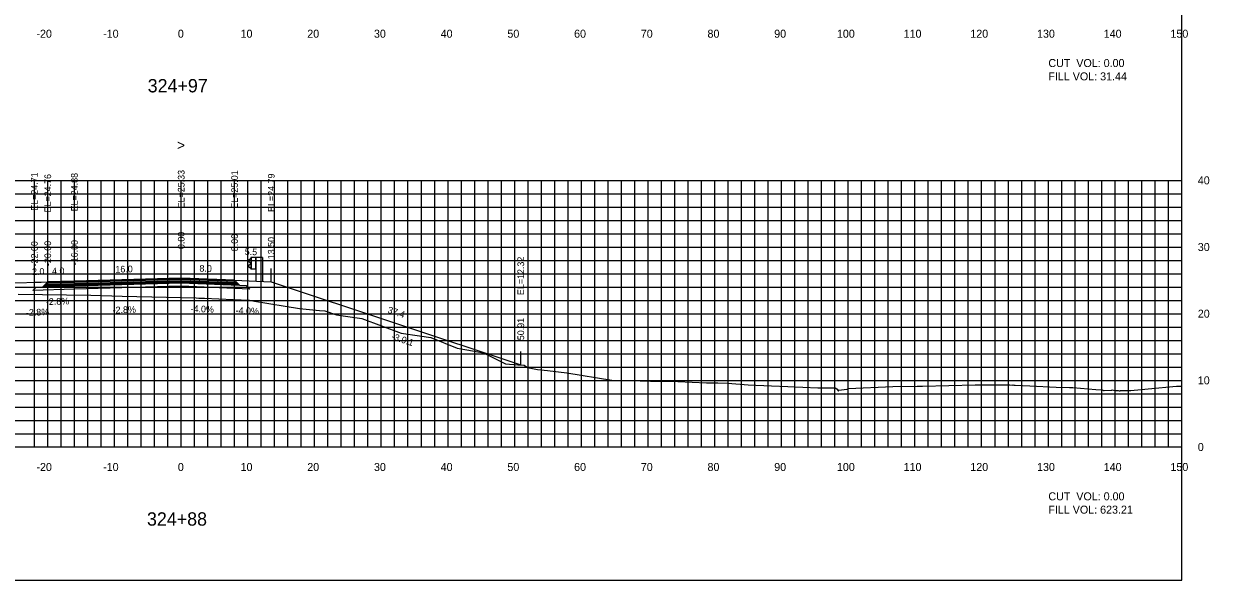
# Model space of a CAD drawing. Extents: x 1797652 to 1804145, y 245981 to 250269.
# Drawn here: x 1803967.4 to 1804145.1, y 250079.4 to 250162.9 of the extents above; entities that cross this region are included whole.
import ezdxf

# ---------------------------------------------------------------- set-up
doc = ezdxf.new("R2010")
doc.units = 0
for name, color, linetype in [('1', 7, 'Continuous'), ('10', 7, 'Continuous'), ('3', 7, 'Continuous'), ('31', 7, 'Continuous'), ('4', 7, 'Continuous'), ('60', 7, 'Continuous'), ('ANNO-TXT', 7, 'Continuous'), ('BASE', 7, 'Continuous'), ('CL-CNST', 7, 'Continuous'), ('Level 1', 7, 'Continuous'), ('Level 62', 7, 'Continuous'), ('LOWER BINDER', 7, 'Continuous'), ('M-ROADS', 7, 'Continuous'), ('UPPER BINDER', 7, 'Continuous'), ('WEARING', 7, 'Continuous')]:
    doc.layers.add(name, color=color, linetype=linetype)

msp = doc.modelspace()

# ---------------------------------------------------------------- linework, layer by layer
for p, q in [((1803971, 250124.19), (1803971, 250126.19)), ((1803975, 250124.31), (1803975, 250126.31)), ((1803991, 250124.76), (1803991, 250126.76)), ((1803999, 250124.44), (1803999, 250126.44)), ((1804004.5, 250124.22), (1804004.5, 250126.22)), ((1803969, 250124.14), (1803969, 250126.14)), ((1804041.91, 250111.75), (1804041.91, 250113.75))]:
    msp.add_line(p, q)
msp.add_lwpolyline([(1803841, 250079.43), (1804141, 250079.43), (1804141, 250269.43), (1803841, 250269.43)], close=True)
at = {"layer": '60'}
for p, q in [((1804141, 250099.43), (1804141, 250139.43)), ((1804141.06, 250139.43), (1804141, 250139.43)), ((1804141.06, 250129.43), (1804141, 250129.43)), ((1804141.06, 250119.43), (1804141, 250119.43)), ((1804141.06, 250109.43), (1804141, 250109.43)), ((1803841, 250099.43), (1804141, 250099.43)), ((1803971, 250099.37), (1803971, 250099.43)), ((1803981, 250099.37), (1803981, 250099.43)), ((1803991, 250099.37), (1803991, 250099.43)), ((1804001, 250099.37), (1804001, 250099.43)), ((1804011, 250099.37), (1804011, 250099.43)), ((1804021, 250099.37), (1804021, 250099.43)), ((1804031, 250099.37), (1804031, 250099.43)), ((1804041, 250099.37), (1804041, 250099.43)), ((1804051, 250099.37), (1804051, 250099.43)), ((1804061, 250099.37), (1804061, 250099.43)), ((1804071, 250099.37), (1804071, 250099.43)), ((1804081, 250099.37), (1804081, 250099.43)), ((1804091, 250099.37), (1804091, 250099.43)), ((1804101, 250099.37), (1804101, 250099.43)), ((1804111, 250099.37), (1804111, 250099.43)), ((1804121, 250099.37), (1804121, 250099.43)), ((1804131, 250099.37), (1804131, 250099.43)), ((1804141, 250099.37), (1804141, 250099.43)), ((1804141.06, 250099.43), (1804141, 250099.43))]:
    msp.add_line(p, q, dxfattribs=at)
at = {"layer": 'BASE'}
msp.add_lwpolyline([(1803969.26, 250123.43), (1803970.26, 250123.45), (1803975, 250123.59), (1803991, 250124.04), (1803999.75, 250123.69), (1804000.75, 250123.65), (1804001.27, 250123.13), (1803991, 250123.54), (1803975, 250123.09), (1803968.75, 250122.91)], close=True, dxfattribs=at)
at = {"layer": 'CL-CNST'}
for points in [[(1803969, 250124.14), (1803971, 250124.19), (1803975, 250124.31), (1803991, 250124.76), (1803999, 250124.44), (1804004.5, 250124.22), (1804041.91, 250111.75)], [(1803965.67, 250124.04), (1803974.37, 250124.28)]]:
    msp.add_lwpolyline(points, dxfattribs=at)
at = {"layer": 'Level 1'}
for p, q in [((1804001.46, 250127.69), (1804001.1, 250127.39)), ((1804001.1, 250127.32), (1804001.46, 250127.03)), ((1804001.46, 250126.89), (1804001.1, 250126.59)), ((1804001.1, 250126.52), (1804001.46, 250126.24)), ((1804001.46, 250127.84), (1804001.46, 250126.09)), ((1804003.21, 250127.84), (1804001.46, 250127.84)), ((1804001.51, 250127.84), (1804001.51, 250126.09)), ((1804002.16, 250127.84), (1804002.16, 250126.09)), ((1804002.21, 250127.84), (1804002.21, 250124.31)), ((1804003.21, 250127.84), (1804003.21, 250124.27)), ((1804002.21, 250126.09), (1804001.46, 250126.09))]:
    msp.add_line(p, q, dxfattribs=at)
for centre in [(1804001.13, 250127.35), (1804001.13, 250126.56)]:
    msp.add_arc(centre, 0.05, 135, 226.6208, dxfattribs=at)
at = {"layer": 'Level 62'}
for p, q in [((1803841, 250139.43), (1804141, 250139.43)), ((1803969, 250099.43), (1803969, 250139.43)), ((1803971, 250099.43), (1803971, 250139.43)), ((1803973, 250099.43), (1803973, 250139.43)), ((1803975, 250099.43), (1803975, 250139.43)), ((1803977, 250099.43), (1803977, 250139.43)), ((1803979, 250099.43), (1803979, 250139.43)), ((1803981, 250099.43), (1803981, 250139.43)), ((1803983, 250099.43), (1803983, 250139.43)), ((1803985, 250099.43), (1803985, 250139.43)), ((1803987, 250099.43), (1803987, 250139.43)), ((1803989, 250099.43), (1803989, 250139.43)), ((1803991, 250099.43), (1803991, 250139.43)), ((1803993, 250099.43), (1803993, 250139.43)), ((1803995, 250099.43), (1803995, 250139.43)), ((1803997, 250099.43), (1803997, 250139.43)), ((1803999, 250099.43), (1803999, 250139.43)), ((1804001, 250099.43), (1804001, 250139.43)), ((1804003, 250099.43), (1804003, 250139.43)), ((1804005, 250099.43), (1804005, 250139.43)), ((1804007, 250099.43), (1804007, 250139.43)), ((1804009, 250099.43), (1804009, 250139.43)), ((1804011, 250099.43), (1804011, 250139.43)), ((1804013, 250099.43), (1804013, 250139.43)), ((1804015, 250099.43), (1804015, 250139.43)), ((1804017, 250099.43), (1804017, 250139.43)), ((1804019, 250099.43), (1804019, 250139.43)), ((1804021, 250099.43), (1804021, 250139.43)), ((1804023, 250099.43), (1804023, 250139.43)), ((1804025, 250099.43), (1804025, 250139.43)), ((1804027, 250099.43), (1804027, 250139.43)), ((1804029, 250099.43), (1804029, 250139.43)), ((1804031, 250099.43), (1804031, 250139.43)), ((1804033, 250099.43), (1804033, 250139.43)), ((1804035, 250099.43), (1804035, 250139.43)), ((1804037, 250099.43), (1804037, 250139.43)), ((1804039, 250099.43), (1804039, 250139.43)), ((1804041, 250099.43), (1804041, 250139.43)), ((1804043, 250099.43), (1804043, 250139.43)), ((1804045, 250099.43), (1804045, 250139.43)), ((1804047, 250099.43), (1804047, 250139.43)), ((1804049, 250099.43), (1804049, 250139.43)), ((1804051, 250099.43), (1804051, 250139.43)), ((1804053, 250099.43), (1804053, 250139.43)), ((1804055, 250099.43), (1804055, 250139.43)), ((1804057, 250099.43), (1804057, 250139.43)), ((1804059, 250099.43), (1804059, 250139.43)), ((1804061, 250099.43), (1804061, 250139.43)), ((1804063, 250099.43), (1804063, 250139.43)), ((1804065, 250099.43), (1804065, 250139.43)), ((1804067, 250099.43), (1804067, 250139.43)), ((1804069, 250099.43), (1804069, 250139.43)), ((1804071, 250099.43), (1804071, 250139.43)), ((1804073, 250099.43), (1804073, 250139.43)), ((1804075, 250099.43), (1804075, 250139.43)), ((1804077, 250099.43), (1804077, 250139.43)), ((1804079, 250099.43), (1804079, 250139.43)), ((1804081, 250099.43), (1804081, 250139.43)), ((1804083, 250099.43), (1804083, 250139.43)), ((1804085, 250099.43), (1804085, 250139.43)), ((1804087, 250099.43), (1804087, 250139.43)), ((1804089, 250099.43), (1804089, 250139.43)), ((1804091, 250099.43), (1804091, 250139.43)), ((1804093, 250099.43), (1804093, 250139.43)), ((1804095, 250099.43), (1804095, 250139.43)), ((1804097, 250099.43), (1804097, 250139.43)), ((1804099, 250099.43), (1804099, 250139.43)), ((1804101, 250099.43), (1804101, 250139.43)), ((1804103, 250099.43), (1804103, 250139.43)), ((1804105, 250099.43), (1804105, 250139.43)), ((1804107, 250099.43), (1804107, 250139.43)), ((1804109, 250099.43), (1804109, 250139.43)), ((1804111, 250099.43), (1804111, 250139.43)), ((1804113, 250099.43), (1804113, 250139.43)), ((1804115, 250099.43), (1804115, 250139.43)), ((1804117, 250099.43), (1804117, 250139.43)), ((1804119, 250099.43), (1804119, 250139.43)), ((1804121, 250099.43), (1804121, 250139.43)), ((1804123, 250099.43), (1804123, 250139.43)), ((1804125, 250099.43), (1804125, 250139.43)), ((1804127, 250099.43), (1804127, 250139.43)), ((1804129, 250099.43), (1804129, 250139.43)), ((1804131, 250099.43), (1804131, 250139.43)), ((1804133, 250099.43), (1804133, 250139.43)), ((1804135, 250099.43), (1804135, 250139.43)), ((1804137, 250099.43), (1804137, 250139.43)), ((1804139, 250099.43), (1804139, 250139.43)), ((1804141, 250099.43), (1804141, 250139.43)), ((1803841, 250137.43), (1804141, 250137.43)), ((1803841, 250135.43), (1804141, 250135.43)), ((1803841, 250133.43), (1804141, 250133.43)), ((1803841, 250131.43), (1804141, 250131.43)), ((1803841, 250129.43), (1804141, 250129.43)), ((1803841, 250127.43), (1804141, 250127.43)), ((1803841, 250125.43), (1804141, 250125.43)), ((1803841, 250123.43), (1804141, 250123.43)), ((1803841, 250121.43), (1804141, 250121.43)), ((1803841, 250119.43), (1804141, 250119.43)), ((1803841, 250117.43), (1804141, 250117.43)), ((1803841, 250115.43), (1804141, 250115.43)), ((1803841, 250113.43), (1804141, 250113.43)), ((1803841, 250111.43), (1804141, 250111.43)), ((1803841, 250109.43), (1804141, 250109.43)), ((1803841, 250107.43), (1804141, 250107.43)), ((1803841, 250105.43), (1804141, 250105.43)), ((1803841, 250103.43), (1804141, 250103.43)), ((1803841, 250101.43), (1804141, 250101.43)), ((1803841, 250099.43), (1804141, 250099.43))]:
    msp.add_line(p, q, dxfattribs=at)
at = {"layer": 'LOWER BINDER'}
for points in [[(1803975, 250123.97), (1803991, 250124.42), (1803999.36, 250124.09), (1803999.55, 250123.89), (1803991, 250124.23), (1803975, 250123.78), (1803970.46, 250123.65), (1803970.65, 250123.85)], [(1803975, 250123.78), (1803991, 250124.23), (1803999.55, 250123.89), (1803999.75, 250123.69), (1803991, 250124.04), (1803975, 250123.59), (1803970.26, 250123.45), (1803970.46, 250123.65)]]:
    msp.add_lwpolyline(points, close=True, dxfattribs=at)
at = {"layer": 'M-ROADS'}
msp.add_lwpolyline([(1803966.58, 250122.36), (1803977.43, 250122.19), (1803982.14, 250122.07), (1803993.22, 250121.8), (1803993.64, 250121.78), (1803994.47, 250121.76), (1803998.79, 250121.57), (1804001.26, 250121.45), (1804001.97, 250121.32), (1804008.74, 250120.22), (1804011.71, 250119.93), (1804012.51, 250119.85), (1804014.26, 250119.24), (1804015.29, 250119.1), (1804018.07, 250118.73), (1804024, 250116.52), (1804026.71, 250116.1), (1804028.43, 250115.84), (1804032.36, 250114.25), (1804033.84, 250113.99), (1804036.32, 250113.55), (1804039.61, 250111.9), (1804041.49, 250111.78), (1804042.41, 250111.72), (1804042.9, 250111.37), (1804044.43, 250111.07), (1804045.92, 250110.9), (1804048.82, 250110.56), (1804055.54, 250109.47), (1804058.94, 250109.4), (1804059.8, 250109.38), (1804061.37, 250109.32), (1804062.18, 250109.31), (1804065.44, 250109.27), (1804069.74, 250109.07), (1804071.45, 250109.04), (1804072.94, 250109.02), (1804075.99, 250108.78), (1804079.49, 250108.59), (1804081.95, 250108.5), (1804086.42, 250108.3), (1804088.06, 250108.32), (1804088.84, 250108.32), (1804088.87, 250108.26), (1804088.97, 250108.34), (1804089.35, 250108.1), (1804089.5, 250107.88), (1804089.51, 250107.84), (1804089.53, 250107.88), (1804089.57, 250107.94), (1804090.77, 250108.13), (1804090.94, 250108.04), (1804091.02, 250108.19), (1804097.68, 250108.5), (1804101.31, 250108.54), (1804102.15, 250108.55), (1804110.03, 250108.75), (1804110.55, 250108.75), (1804112.65, 250108.75), (1804114.9, 250108.75), (1804115.04, 250108.75), (1804115.19, 250108.75), (1804115.2, 250108.75), (1804115.63, 250108.71), (1804115.69, 250108.75), (1804115.84, 250108.73), (1804116.04, 250108.69), (1804118.23, 250108.63), (1804122.19, 250108.39), (1804124.16, 250108.37), (1804124.68, 250108.37), (1804128.13, 250108.04), (1804129.08, 250108), (1804129.28, 250107.93), (1804129.35, 250107.93), (1804130.51, 250107.97), (1804130.57, 250108.01), (1804130.95, 250107.92), (1804131.32, 250107.91), (1804131.46, 250107.91), (1804131.6, 250107.88), (1804131.78, 250107.85), (1804131.8, 250107.93), (1804131.81, 250107.93), (1804131.95, 250107.93), (1804133.38, 250107.93), (1804135.94, 250108.17), (1804140.2, 250108.56), (1804140.92, 250108.56), (1804141, 250108.59)], dxfattribs=at)
at = {"layer": 'UPPER BINDER'}
msp.add_lwpolyline([(1803999.36, 250124.09), (1803999.16, 250124.29), (1803991, 250124.61), (1803975, 250124.16), (1803970.85, 250124.04), (1803970.65, 250123.85), (1803975, 250123.97), (1803991, 250124.42)], close=True, dxfattribs=at)
at = {"layer": 'WEARING'}
msp.add_lwpolyline([(1803999.16, 250124.29), (1803999, 250124.44), (1803991, 250124.76), (1803975, 250124.31), (1803971, 250124.19), (1803970.85, 250124.04), (1803975, 250124.16), (1803991, 250124.61)], close=True, dxfattribs=at)

# ---------------------------------------------------------------- texts
msp.add_text('-3.0:1', height=1, rotation=341.5652).set_placement((1804022.41, 250115.62))
at = {"layer": '1'}
for s, p in [('324+97', (1803985.98, 250152.63)), ('324+88', (1803985.87, 250087.63))]:
    msp.add_text(s, height=2, dxfattribs=at).set_placement(p)
at = {"layer": '10'}
for s, p in [('-20', (1803969.3, 250160.83)), ('-10', (1803979.3, 250160.83)), ('0', (1803990.5, 250160.83)), ('10', (1803999.9, 250160.83)), ('20', (1804009.9, 250160.83)), ('30', (1804019.9, 250160.83)), ('40', (1804029.9, 250160.83)), ('50', (1804039.9, 250160.83)), ('60', (1804049.9, 250160.83)), ('70', (1804059.9, 250160.83)), ('80', (1804069.9, 250160.83)), ('90', (1804079.9, 250160.83)), ('100', (1804089.3, 250160.83)), ('110', (1804099.3, 250160.83)), ('120', (1804109.3, 250160.83)), ('130', (1804119.3, 250160.83)), ('140', (1804129.3, 250160.83)), ('150', (1804139.3, 250160.83)), ('-20', (1803969.3, 250095.83)), ('-10', (1803979.3, 250095.83)), ('0', (1803990.5, 250095.83)), ('10', (1803999.9, 250095.83)), ('20', (1804009.9, 250095.83)), ('30', (1804019.9, 250095.83)), ('40', (1804029.9, 250095.83)), ('50', (1804039.9, 250095.83)), ('60', (1804049.9, 250095.83)), ('70', (1804059.9, 250095.83)), ('80', (1804069.9, 250095.83)), ('90', (1804079.9, 250095.83)), ('100', (1804089.3, 250095.83)), ('110', (1804099.3, 250095.83)), ('120', (1804109.3, 250095.83)), ('130', (1804119.3, 250095.83)), ('140', (1804129.3, 250095.83)), ('150', (1804139.3, 250095.83))]:
    msp.add_text(s, height=1.2, dxfattribs=at).set_placement(p)
at = {"layer": '3'}
for s, p in [('EL=24.71', (1803969.5, 250134.86)), ('EL=24.88', (1803975.5, 250134.78)), ('EL=25.33', (1803991.5, 250135.23)), ('EL=25.01', (1803999.5, 250135.17)), ('EL=24.79', (1804005, 250134.69)), ('EL=24.76', (1803971.5, 250134.62)), ('0.00', (1803991.5, 250129.12)), ('-22.00', (1803969.5, 250126.52)), ('-20.00', (1803971.5, 250126.57)), ('-16.00', (1803975.5, 250126.69)), ('8.00', (1803999.5, 250128.8)), ('13.50', (1804005, 250127.59)), ('EL=12.32', (1804042.41, 250122.22)), ('50.91', (1804042.41, 250115.45))]:
    msp.add_text(s, height=1, rotation=90, dxfattribs=at).set_placement(p)
at = {"layer": '31'}
for s, p in [('40', (1804143.4, 250138.83)), ('30', (1804143.4, 250128.83)), ('20', (1804143.4, 250118.83)), ('10', (1804143.4, 250108.83)), ('0', (1804143.4, 250098.83))]:
    msp.add_text(s, height=1.2, dxfattribs=at).set_placement(p)
at = {"layer": '4'}
for s, rotation, p in [('5.5', 357.7094, (1804000.51, 250128.26)), ('2.0', 1.6219, (1803968.65, 250125.23)), ('4.0', 1.6219, (1803971.65, 250125.31)), ('16.0', 1.6219, (1803981.15, 250125.58)), ('8.0', 357.7094, (1803993.72, 250125.75)), ('-2.8%', 1.6219, (1803970.73, 250120.73)), ('-2.8%', 1.6219, (1803967.73, 250119.1)), ('-2.8%', 1.6219, (1803980.73, 250119.47)), ('-4.0%', 357.7094, (1803992.39, 250119.7)), ('-4.0%', 357.7094, (1803999.14, 250119.43)), ('37.4', 341.5652, (1804021.86, 250119.59))]:
    msp.add_text(s, height=1, rotation=rotation, dxfattribs=at).set_placement(p)
at = {"layer": '60'}
msp.add_text('>', height=1.5, dxfattribs=at).set_placement((1803990.39, 250143.97))
at = {"layer": 'ANNO-TXT'}
for s, p in [('CUT  VOL: 0.00', (1804121, 250156.43)), ('FILL VOL: 31.44', (1804121, 250154.43)), ('CUT  VOL: 0.00', (1804121, 250091.43)), ('FILL VOL: 623.21', (1804121, 250089.43))]:
    msp.add_text(s, height=1.2, dxfattribs=at).set_placement(p)

doc.saveas('drawing.dxf')
